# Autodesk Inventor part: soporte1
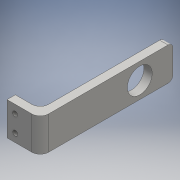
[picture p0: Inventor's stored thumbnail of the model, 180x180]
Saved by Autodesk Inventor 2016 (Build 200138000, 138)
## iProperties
Created: 2016-06
Part Number: soporte1
Material: Generic
Document SubType Name: Modeling
Designer: yesi alvarez
Mass: 9.37466 g
Surface Area: 49.4252 cm^2
Volume: 9.37466 cm^3
Density: 1 g/cm^3
Appearance: Default
Author: yesi alvarez
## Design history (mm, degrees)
sketch "Sketch1"
  geometry: 1 further point
sketch "Sketch2"
  geometry: L1 (-0.71, -25)-(-3.437, -25); L2 (1.563, -20)-(1.562, 55); L3 (1.562, 55)-(-3.438, 55); L4 (-3.438, 55)-(-3.437, -15); L5 (-0.71, -25)-(1.562, 55); L6 (1.563, -25)-(-3.438, 55); L7 (-3.437, -25)-(-18.437, -25); L8 (-18.437, -25)-(-18.437, -20); L9 (-18.437, -20)-(-8.437, -20); L10 (1.563, -20)-(1.563, -20); A1 r 5 centre (-8.437, -15) between (-8.437, -20) and (-3.437, -15); A2 r 5 centre (-3.437, -20) between (-3.437, -25) and (1.563, -20); 1 further point
  constraints: 20 end point, 4 parallel, 4 point on circle, 4 point on line, 4 tangent, 2 centre point, 2 horizontal, 2 perpendicular
  dimensions: "d0" = 5 distance of L3.end L2.end; "d1" = 80 distance of L2.end L6.start; "d2" = 20 distance of L8.end L10.start; "d3" = 5 distance of L7.end L8.end; "d4" = 5 radius of A1; "d5" = 5 radius of A2
extrude "Extrusion1" new body sketch "Sketch2" distance "d6" = 20; taper "d7" = 0 deg
fillet "Fillet1" dims "d8" = 3
sketch "Sketch3"
  geometry: L1 (0, 0)-(0, 67) reference; L2 (3, 70)-(17, 70) reference; C1 r 7.5 at (10, 50); 2 further points
  constraints: 1 centre point, 1 coincident
  dimensions: "d9" = 10 distance from line of point (10, 50) L1; "d10" = 20 distance from line of point (10, 50) L2; "d11" = 15 diameter of C1
extrude "Extrusion2" cut sketch "Sketch3" distance "d12" = 10; taper "d13" = 0 deg
sketch "Sketch4"
  geometry: L1 (0, 0)-(0, -20) reference; L2 (0, 0)-(10, 0) reference; L3 (10, -20)-(0, -20) reference; C1 r 1.5 at (5, -5); C2 r 1.5 at (4.877, -15); 3 further points
  constraints: 2 centre point, 2 coincident
  dimensions: "d16" = 5 distance from line of point (5, -5) L1; "d17" = 5 distance from line of point (5, -5) L2; "d19" = 3 diameter of C1; "d20" = 3 diameter of C2; "d27" = 5 distance from line of C2.centre L3
extrude "Extrusion3" cut sketch "Sketch4" distance "d21" = 10; taper "d22" = 0 deg
thread "Thread2" dims "d23" = 10, "d24" = 0
thread "Thread3" dims "d25" = 10, "d26" = 0
body "Solid1"
